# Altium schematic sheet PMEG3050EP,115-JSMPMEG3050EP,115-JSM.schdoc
size 127 x 101 mm
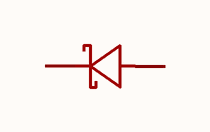
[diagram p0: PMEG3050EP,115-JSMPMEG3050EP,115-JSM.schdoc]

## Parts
D?  pmeg3050ep,115-jsm  [SOD-128_L3.7-W2.5-LS4.7-RD]  (value not drawn)

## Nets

Not connected (* = marked no-connect by the designer): D? 1(C) 2(A)

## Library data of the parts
D? = pmeg3050ep,115-jsm: 二极管配置:1个独立式;正向压降(Vf):700mV@3A;直流反向耐压(Vr):60V;整流电流:3A;; Manufacturer: JSMSEMI(杰盛微); AddInBom: yes; ModelId: 0bf321a6742b41739afac8716a45ef86; ModelName: SOD-128_L3.7-W2.5-LS4.7-RD-1; ModelTransform: 185.039,98.05051,0,0,0,0,0,0,0; Diode Configuration: 1个独立式; Voltage - DC Reverse(Vr): 60V; Current - Rectified: 3A; Reverse Leakage Current (Ir): 350uA@60V; Operating Junction Temperature Range: -55℃~+125℃; Non-Repetitive Peak Forward Surge Current: 80A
